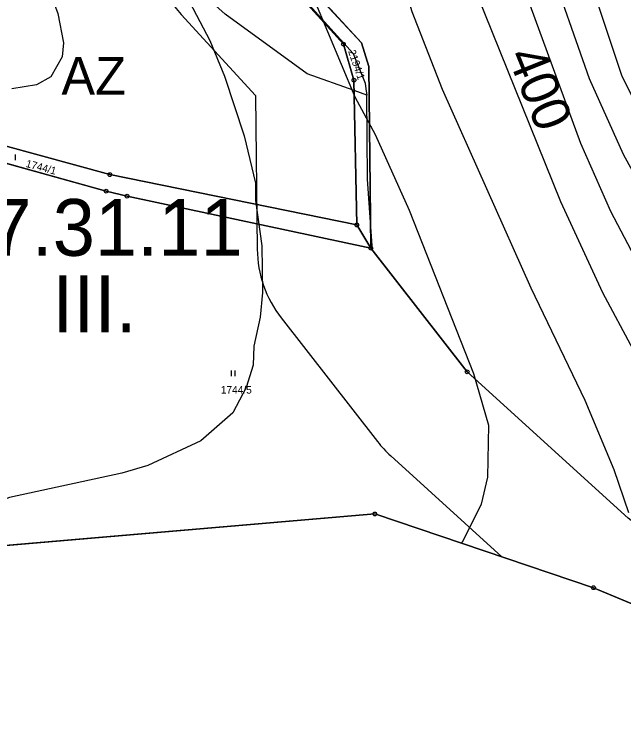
# Model space of a CAD drawing. Extents: x -706130 to -698555, y -971544 to -967260.
# Drawn here: x -703308.5 to -703147.5, y -971046.6 to -970857.1 of the extents above; entities that cross this region are included whole.
import ezdxf

# ---------------------------------------------------------------- set-up
doc = ezdxf.new("R2010")
doc.units = 0
for name, color, linetype in [('BPEJ hranice S', 7, 'Continuous'), ('BPEJ kód', 7, 'Continuous'), ('Hranice řešeného území', 7, 'Continuous'), ('KN_Hranice obce', 7, 'Continuous'), ('KN_Hranice_katastrální území', 7, 'Continuous'), ('KN_Hranice_parcel', 7, 'Continuous'), ('KN_Parcelni cisla', 7, 'Continuous'), ('KN_Polygon parcely', 7, 'Continuous'), ('KN_POZEMKY_10_LESNI POZEMEK', 7, 'Continuous'), ('KN_POZEMKY_14_OSTATNI PLOCHA', 7, 'Continuous'), ('KN_POZEMKY_7_TTP', 7, 'Continuous'), ('KN_VYUZITI_17_ostatni plocha_ostatni komunikace', 7, 'Continuous'), ('KN_Značky bodu BP', 7, 'Continuous'), ('KN_Značky kultur', 7, 'Continuous'), ('OP lesa 30 m', 7, 'Continuous'), ('Plochy lesní všeobecné S', 7, 'Continuous'), ('Plochy smíšené nezastavěného území všeobecné S', 7, 'Continuous'), ('Plochy zemědělské všeobecné CELEK S', 7, 'Continuous'), ('Povodi vodniho toku S', 7, 'Continuous'), ('Regulační bloky v krajině S', 7, 'Continuous'), ('Regulační kódy v krajině S', 7, 'Continuous'), ('VÝŠKOPIS_vrstevnice hlavní', 7, 'Continuous'), ('VÝŠKOPIS_vrstevnice výška', 7, 'Continuous'), ('VÝŠKOPIS_vrstevnice zesílená', 7, 'Continuous')]:
    doc.layers.add(name, color=color, linetype=linetype)

msp = doc.modelspace()

# ---------------------------------------------------------------- linework, layer by layer
at = {"layer": 'BPEJ hranice S'}
for points in [[(-703146.34, -970990.21), (-703188.87, -970951.52), (-703213.89, -970919.41), (-703214.4, -970912.01), (-703215.2, -970900.58), (-703215.37, -970878.39), (-703218.72, -970877.19), (-703231.11, -970872.76), (-703252.79, -970857.03), (-703269.59, -970841.85), (-703291.81, -970808.23), (-703299.14, -970791.84), (-703301.03, -970787.62), (-703323.79, -970764.31)], [(-703238.22, -970846.15), (-703219.02, -970867.46), (-703215.83, -970875.27), (-703215.61, -970876.73), (-703215.37, -970878.39), (-703218.72, -970877.19), (-703231.11, -970872.76), (-703252.79, -970857.03)], [(-703382.49, -970993.97), (-703382.44, -970993.97), (-703380.74, -970993.98), (-703327.73, -970998.95), (-703314.92, -970997.75), (-703213.28, -970989.07), (-703155.48, -971008.55), (-703136.46, -971016.54), (-703118.51, -971025.64), (-703110.66, -971029.62)]]:
    msp.add_lwpolyline(points, dxfattribs=at)
at = {"layer": 'Hranice řešeného území'}
msp.add_lwpolyline([(-703136.46, -971016.54), (-703155.48, -971008.55), (-703213.28, -970989.07), (-703314.92, -970997.75), (-703327.73, -970998.95), (-703380.74, -970993.98), (-703382.44, -970993.97), (-703386.57, -970993.95), (-703392.54, -970993.91), (-703394.33, -970993.9), (-703405.07, -970994.15), (-703417, -970993.25), (-703427.1, -970990.31), (-703478.14, -970955.69), (-703518.72, -970928.16), (-703520.57, -970926.9), (-703526.54, -970922.83), (-703552.19, -970905.36), (-703588.47, -970877.49), (-703614.35, -970903.64), (-703634.1, -970919.81)], dxfattribs=at)
at = {"layer": 'KN_Hranice obce'}
msp.add_lwpolyline([(-703634.1, -970919.81), (-703614.35, -970903.64), (-703588.47, -970877.49), (-703552.19, -970905.36), (-703526.54, -970922.83), (-703520.57, -970926.9), (-703518.72, -970928.16), (-703478.14, -970955.69), (-703427.1, -970990.31), (-703417, -970993.25), (-703405.07, -970994.15), (-703394.33, -970993.9), (-703392.54, -970993.91), (-703386.57, -970993.95), (-703382.44, -970993.97), (-703380.74, -970993.98), (-703327.73, -970998.95), (-703314.92, -970997.75), (-703213.28, -970989.07), (-703155.48, -971008.55), (-703136.46, -971016.54)], dxfattribs=at)
at = {"layer": 'KN_Hranice_katastrální území'}
msp.add_lwpolyline([(-703634.1, -970919.81), (-703614.35, -970903.64), (-703588.47, -970877.49), (-703552.19, -970905.36), (-703526.54, -970922.83), (-703520.57, -970926.9), (-703518.72, -970928.16), (-703478.14, -970955.69), (-703427.1, -970990.31), (-703417, -970993.25), (-703405.07, -970994.15), (-703394.33, -970993.9), (-703392.54, -970993.91), (-703386.57, -970993.95), (-703382.44, -970993.97), (-703380.74, -970993.98), (-703327.73, -970998.95), (-703314.92, -970997.75), (-703213.28, -970989.07), (-703155.48, -971008.55), (-703136.46, -971016.54)], dxfattribs=at)
at = {"layer": 'KN_Hranice_parcel'}
for p, q in [((-703283.26, -970899.43), (-703311.29, -970891.69)), ((-703218.04, -970912.72), (-703283.26, -970899.43)), ((-703278.74, -970905.1), (-703214.33, -970918.84)), ((-703214.33, -970918.84), (-703218.04, -970912.72))]:
    msp.add_line(p, q, dxfattribs=at)
for points in [[(-703218.04, -970912.72), (-703218.77, -970874.45), (-703221.56, -970864.95), (-703246.9, -970836.79)], [(-703242.32, -970836.8), (-703216.79, -970864.63), (-703214.84, -970870.83), (-703214.33, -970918.84)], [(-703324.83, -970892.5), (-703284.24, -970903.8), (-703278.74, -970905.1)], [(-703118.51, -971025.64), (-703116.04, -971013.3), (-703138.08, -970996.69), (-703146.34, -970990.21), (-703188.87, -970951.52), (-703214.33, -970918.84)], [(-703314.92, -970997.75), (-703213.28, -970989.07), (-703155.48, -971008.55), (-703136.46, -971016.54), (-703118.51, -971025.64)]]:
    msp.add_lwpolyline(points, dxfattribs=at)
at = {"layer": 'KN_Polygon parcely'}
msp.add_lwpolyline([(-703142.86, -970683.51), (-703168.87, -970735.8), (-703193.88, -970758.14), (-703201.19, -970768.01), (-703208.3, -970792.34), (-703211.64, -970831.19), (-703242.32, -970836.8), (-703216.79, -970864.63), (-703214.84, -970870.83), (-703214.33, -970918.84), (-703188.87, -970951.52), (-703146.34, -970990.21)], dxfattribs=at)
for points in [[(-703218.77, -970874.45), (-703221.56, -970864.95), (-703246.9, -970836.79), (-703252.48, -970822.52), (-703251.36, -970811.71), (-703338.12, -970775.63), (-703354.08, -970769.21), (-703356.16, -970787.98), (-703355, -970796.22), (-703358.84, -970830.72), (-703361.41, -970853.84), (-703322.73, -970883.71), (-703325.48, -970887.18), (-703311.29, -970891.69), (-703283.26, -970899.43), (-703218.04, -970912.72)], [(-703246.9, -970836.79), (-703221.56, -970864.95), (-703218.77, -970874.45), (-703218.04, -970912.72), (-703214.33, -970918.84), (-703214.84, -970870.83), (-703216.79, -970864.63), (-703242.32, -970836.8)], [(-703218.04, -970912.72), (-703283.26, -970899.43), (-703311.29, -970891.69), (-703325.48, -970887.18), (-703359.8, -970881.15), (-703359.88, -970886.03), (-703324.83, -970892.5), (-703284.24, -970903.8), (-703278.74, -970905.1), (-703214.33, -970918.84)], [(-703116.04, -971013.3), (-703138.08, -970996.69), (-703146.34, -970990.21), (-703188.87, -970951.52), (-703214.33, -970918.84), (-703278.74, -970905.1), (-703284.24, -970903.8), (-703324.83, -970892.5), (-703359.88, -970886.03), (-703368.03, -970914.24), (-703318.27, -970925.22), (-703314.92, -970997.75), (-703213.28, -970989.07), (-703155.48, -971008.55), (-703136.46, -971016.54), (-703118.51, -971025.64)]]:
    msp.add_lwpolyline(points, close=True, dxfattribs=at)
at = {"layer": 'KN_POZEMKY_10_LESNI POZEMEK'}
for p, q in [((-703216.79, -970864.63), (-703242.32, -970836.8)), ((-703214.84, -970870.83), (-703216.79, -970864.63)), ((-703214.33, -970918.84), (-703214.84, -970870.83)), ((-703188.87, -970951.52), (-703214.33, -970918.84)), ((-703146.34, -970990.21), (-703188.87, -970951.52))]:
    msp.add_line(p, q, dxfattribs=at)
at = {"layer": 'KN_POZEMKY_14_OSTATNI PLOCHA'}
for p, q in [((-703221.56, -970864.95), (-703246.9, -970836.79)), ((-703242.32, -970836.8), (-703216.79, -970864.63)), ((-703218.77, -970874.45), (-703221.56, -970864.95)), ((-703216.79, -970864.63), (-703214.84, -970870.83)), ((-703214.84, -970870.83), (-703214.33, -970918.84)), ((-703218.04, -970912.72), (-703218.77, -970874.45)), ((-703214.33, -970918.84), (-703218.04, -970912.72))]:
    msp.add_line(p, q, dxfattribs=at)
at = {"layer": 'KN_POZEMKY_7_TTP'}
for p, q in [((-703246.9, -970836.79), (-703221.56, -970864.95)), ((-703221.56, -970864.95), (-703218.77, -970874.45)), ((-703218.77, -970874.45), (-703218.04, -970912.72)), ((-703284.24, -970903.8), (-703324.83, -970892.5)), ((-703324.83, -970892.5), (-703284.24, -970903.8)), ((-703311.29, -970891.69), (-703283.26, -970899.43)), ((-703283.26, -970899.43), (-703311.29, -970891.69)), ((-703283.26, -970899.43), (-703218.04, -970912.72)), ((-703218.04, -970912.72), (-703283.26, -970899.43)), ((-703278.74, -970905.1), (-703284.24, -970903.8)), ((-703284.24, -970903.8), (-703278.74, -970905.1)), ((-703214.33, -970918.84), (-703278.74, -970905.1)), ((-703278.74, -970905.1), (-703214.33, -970918.84)), ((-703218.04, -970912.72), (-703214.33, -970918.84)), ((-703214.33, -970918.84), (-703188.87, -970951.52)), ((-703188.87, -970951.52), (-703146.34, -970990.21)), ((-703213.28, -970989.07), (-703314.92, -970997.75)), ((-703155.48, -971008.55), (-703213.28, -970989.07)), ((-703136.46, -971016.54), (-703155.48, -971008.55))]:
    msp.add_line(p, q, dxfattribs=at)
at = {"layer": 'KN_VYUZITI_17_ostatni plocha_ostatni komunikace'}
for p, q in [((-703221.56, -970864.95), (-703246.9, -970836.79)), ((-703242.32, -970836.8), (-703216.79, -970864.63)), ((-703218.77, -970874.45), (-703221.56, -970864.95)), ((-703216.79, -970864.63), (-703214.84, -970870.83)), ((-703214.84, -970870.83), (-703214.33, -970918.84)), ((-703218.04, -970912.72), (-703218.77, -970874.45)), ((-703214.33, -970918.84), (-703218.04, -970912.72))]:
    msp.add_line(p, q, dxfattribs=at)
at = {"layer": 'KN_Značky bodu BP'}
for centre, radius in [((-703221.56, -970864.95), 0.5), ((-703221.56, -970864.95), 0.0303), ((-703218.77, -970874.45), 0.5), ((-703218.77, -970874.45), 0.0303), ((-703283.26, -970899.43), 0.5), ((-703283.26, -970899.43), 0.0303), ((-703284.24, -970903.8), 0.5), ((-703284.24, -970903.8), 0.0303), ((-703278.74, -970905.1), 0.5), ((-703278.74, -970905.1), 0.0303), ((-703218.04, -970912.72), 0.5), ((-703218.04, -970912.72), 0.0303), ((-703214.33, -970918.84), 0.5), ((-703214.33, -970918.84), 0.0303), ((-703188.87, -970951.52), 0.5), ((-703188.87, -970951.52), 0.0303), ((-703213.28, -970989.07), 0.5), ((-703213.28, -970989.07), 0.0303), ((-703155.48, -971008.55), 0.5), ((-703155.48, -971008.55), 0.0303)]:
    msp.add_circle(centre, radius, dxfattribs=at)
at = {"layer": 'KN_Značky kultur'}
for p, q in [((-703308.16, -970895.59), (-703308.16, -970894.09)), ((-703251.13, -970952.69), (-703251.13, -970951.19)), ((-703250.13, -970952.69), (-703250.13, -970951.19))]:
    msp.add_line(p, q, dxfattribs=at)
at = {"layer": 'OP lesa 30 m'}
for p, q in [((-703238, -970937.28), (-703212.54, -970969.96)), ((-703209.06, -970973.71), (-703179.75, -971000.37))]:
    msp.add_line(p, q, dxfattribs=at)
msp.add_lwpolyline([(-703264.43, -970857.08), (-703244.76, -970878.52), (-703244.33, -970919.16)], dxfattribs=at)
for centre, start, end in [((-703242.32, -970836.8), 100.3624, 222.5319), ((-703214.33, -970918.84), 180.6086, 217.9211), ((-703188.87, -970951.52), 217.9211, 227.7069)]:
    msp.add_arc(centre, 30, start, end, dxfattribs=at)
at = {"layer": 'Plochy lesní všeobecné S'}
for p, q in [((-703242.32, -970836.8), (-703216.79, -970864.63)), ((-703216.79, -970864.63), (-703214.84, -970870.83)), ((-703214.84, -970870.83), (-703214.33, -970918.84)), ((-703214.33, -970918.84), (-703188.87, -970951.52)), ((-703188.87, -970951.52), (-703146.34, -970990.21))]:
    msp.add_line(p, q, dxfattribs=at)
at = {"layer": 'Plochy smíšené nezastavěného území všeobecné S'}
for p, q in [((-703246.9, -970836.79), (-703221.56, -970864.95)), ((-703221.56, -970864.95), (-703218.77, -970874.45)), ((-703218.77, -970874.45), (-703218.04, -970912.72))]:
    msp.add_line(p, q, dxfattribs=at)
for points in [[(-703214.84, -970870.83), (-703216.79, -970864.63), (-703242.32, -970836.8)], [(-703218.04, -970912.72), (-703214.33, -970918.84), (-703214.84, -970870.83)]]:
    msp.add_lwpolyline(points, dxfattribs=at)
at = {"layer": 'Plochy zemědělské všeobecné CELEK S'}
for p, q in [((-703221.56, -970864.95), (-703246.9, -970836.79)), ((-703218.77, -970874.45), (-703221.56, -970864.95)), ((-703218.04, -970912.72), (-703218.77, -970874.45)), ((-703214.33, -970918.84), (-703218.04, -970912.72)), ((-703188.87, -970951.52), (-703214.33, -970918.84)), ((-703146.34, -970990.21), (-703188.87, -970951.52)), ((-703314.92, -970997.75), (-703213.28, -970989.07)), ((-703213.28, -970989.07), (-703155.48, -971008.55)), ((-703155.48, -971008.55), (-703136.46, -971016.54))]:
    msp.add_line(p, q, dxfattribs=at)
at = {"layer": 'Povodi vodniho toku S'}
msp.add_lwpolyline([(-703634.1, -970919.81), (-703614.35, -970903.64), (-703588.47, -970877.49), (-703552.19, -970905.36), (-703526.54, -970922.83), (-703520.57, -970926.9), (-703518.72, -970928.16), (-703478.14, -970955.69), (-703427.1, -970990.31), (-703417, -970993.25), (-703405.07, -970994.15), (-703394.33, -970993.9), (-703392.54, -970993.91), (-703386.57, -970993.95), (-703382.44, -970993.97), (-703380.74, -970993.98), (-703327.73, -970998.95), (-703314.92, -970997.75), (-703213.28, -970989.07), (-703155.48, -971008.55), (-703136.46, -971016.54)], dxfattribs=at)
at = {"layer": 'Regulační bloky v krajině S'}
for p, q in [((-703246.9, -970836.79), (-703221.56, -970864.95)), ((-703221.56, -970864.95), (-703246.9, -970836.79)), ((-703242.32, -970836.8), (-703216.79, -970864.63)), ((-703221.56, -970864.95), (-703218.77, -970874.45)), ((-703218.77, -970874.45), (-703221.56, -970864.95)), ((-703216.79, -970864.63), (-703214.84, -970870.83)), ((-703214.84, -970870.83), (-703214.33, -970918.84)), ((-703218.77, -970874.45), (-703218.04, -970912.72)), ((-703218.04, -970912.72), (-703218.77, -970874.45)), ((-703214.33, -970918.84), (-703218.04, -970912.72)), ((-703214.33, -970918.84), (-703188.87, -970951.52)), ((-703188.87, -970951.52), (-703214.33, -970918.84)), ((-703188.87, -970951.52), (-703146.34, -970990.21)), ((-703146.34, -970990.21), (-703188.87, -970951.52)), ((-703314.92, -970997.75), (-703213.28, -970989.07)), ((-703213.28, -970989.07), (-703155.48, -971008.55)), ((-703155.48, -971008.55), (-703136.46, -971016.54))]:
    msp.add_line(p, q, dxfattribs=at)
for points in [[(-703214.84, -970870.83), (-703216.79, -970864.63), (-703242.32, -970836.8)], [(-703218.04, -970912.72), (-703214.33, -970918.84), (-703214.84, -970870.83)]]:
    msp.add_lwpolyline(points, dxfattribs=at)
at = {"layer": 'VÝŠKOPIS_vrstevnice hlavní'}
for points in [[(-703198.72, -970576.45), (-703211.02, -970605.08), (-703213.45, -970624.92), (-703214.16, -970648.88), (-703216.01, -970666.57), (-703222.43, -970700.82), (-703234.99, -970741.91), (-703239.41, -970759.88), (-703241.27, -970773.86), (-703241.69, -970793.98), (-703242.26, -970794.12), (-703241.69, -970794.41), (-703240.98, -970806.96), (-703237.98, -970824.94), (-703229.42, -970852.9), (-703218.58, -970878.87), (-703213.16, -970888.86), (-703204.17, -970908.83), (-703187.19, -970951.92), (-703183.2, -970965.61), (-703183.48, -970979.31), (-703185.2, -970986.44), (-703190.05, -970996.29), (-703190.45, -970996.77)], [(-703162.26, -970590.2), (-703172.07, -970600.66), (-703177.92, -970609.79), (-703180.06, -970614.36), (-703181.77, -970621.21), (-703185.05, -970641.75), (-703185.77, -970664.58), (-703187.05, -970680.56), (-703190.19, -970698.82), (-703196.75, -970723.93), (-703204.46, -970744.47), (-703210.45, -970758.17), (-703214.3, -970769.58), (-703217.15, -970785.56), (-703217.15, -970799.26), (-703214.3, -970817.52), (-703210.45, -970833.5), (-703203.46, -970856.33), (-703195.47, -970876.87), (-703172.07, -970929.37), (-703157.8, -970959.05), (-703150.1, -970977.31), (-703146.25, -970988.72)], [(-703256.82, -970608.94), (-703254.68, -970630.05), (-703254.68, -970638.9), (-703256.39, -970661.72), (-703258.39, -970675.99), (-703263.24, -970695.96), (-703278.5, -970738.77), (-703284.78, -970762.16), (-703286.63, -970780.43), (-703285.49, -970794.69), (-703280.21, -970814.67), (-703273.79, -970831.79), (-703256.82, -970864.03), (-703252.96, -970873.45), (-703247.83, -970889.14), (-703244.83, -970901.7), (-703244.83, -970906.26), (-703243.12, -970918.25), (-703242.98, -970930.52), (-703243.55, -970937.08), (-703245.26, -970944.78), (-703245.4, -970949.78), (-703247.26, -970955.63), (-703250.82, -970962.33)], [(-703084.36, -970625.93), (-703101.73, -970634.62), (-703114.29, -970644.89), (-703124.56, -970657.16), (-703135.05, -970673.35), (-703141.25, -970685.69), (-703148.53, -970702.81), (-703159.66, -970734.2), (-703168.65, -970754.18), (-703174.92, -970770.15), (-703180.06, -970790.13), (-703181.77, -970804.11), (-703181.2, -970818.66), (-703177.21, -970839.21), (-703174.21, -970849.19), (-703158.94, -970891.14), (-703150.96, -970909.12), (-703144.68, -970921.1), (-703102.73, -970989.87), (-703093.03, -971009.27), (-703086.33, -971024.68), (-703082.9, -971034.95), (-703082.05, -971043.51), (-703082.43, -971046.58)], [(-703141.54, -970732.2), (-703155.52, -970756.6), (-703163.51, -970773.44), (-703168.5, -970789.27), (-703171.36, -970805.25), (-703171.93, -970816.95), (-703169.93, -970832.64), (-703167.79, -970842.06), (-703156.66, -970874.02), (-703147.67, -970893.99), (-703137.83, -970911.97)], [(-703147.1, -970759.03), (-703156.52, -970777.29), (-703159.8, -970786.42), (-703162.94, -970806.96), (-703162.94, -970816.09), (-703162.23, -970822.94), (-703155.66, -970850.34), (-703148.1, -970873.16), (-703139.11, -970891.42)], [(-703318.17, -970808.1), (-703306.47, -970831.22), (-703297.05, -970856.9), (-703295.48, -970864.6), (-703295.91, -970868.31), (-703298.9, -970873.59), (-703302.61, -970875.73), (-703309.18, -970876.73)], [(-703250.82, -970962.33), (-703259.24, -970969.75), (-703273.22, -970976.31), (-703280.07, -970978.31), (-703309.75, -970984.73), (-703327.01, -970991.01), (-703337.14, -970997), (-703338.18, -970997.97)]]:
    msp.add_lwpolyline(points, dxfattribs=at)
at = {"layer": 'VÝŠKOPIS_vrstevnice zesílená'}
msp.add_lwpolyline([(-703150.38, -970633.76), (-703154.24, -970645.75), (-703157.23, -970657.73), (-703163.37, -970693.68), (-703171.36, -970723.64), (-703182.06, -970747.61), (-703191.19, -970772.15), (-703192.76, -970778.43), (-703195.18, -970803.54), (-703194.9, -970816.09), (-703193.19, -970828.65), (-703188.34, -970846.63), (-703164.22, -970906.55), (-703153.1, -970930.52), (-703137.12, -970960.48), (-703122.71, -970984.45), (-703116.57, -970997), (-703111.58, -971009.56), (-703110.15, -971015.83), (-703109.58, -971022.11), (-703110.01, -971028.39), (-703110.43, -971029.75)], dxfattribs=at)

# ---------------------------------------------------------------- texts
at = {"layer": 'BPEJ kód'}
for s, p in [('7.31.11', (-703315.09, -970920.87)), ('III.', (-703298.48, -970941.06))]:
    msp.add_text(s, height=15, dxfattribs=at).set_placement(p)
at = {"layer": 'KN_Parcelni cisla'}
for s, rotation, p in [('2194/1', 289, (-703220.36, -970866.82)), ('1744/1', 345, (-703305.63, -970897.36))]:
    msp.add_text(s, height=2, rotation=rotation, dxfattribs=at).set_placement(p)
msp.add_text('1744/5', height=2, dxfattribs=at).set_placement((-703253.96, -970957.28))
at = {"layer": 'Regulační kódy v krajině S'}
msp.add_text('AZ', height=10, dxfattribs=at).set_placement((-703296.08, -970878.34))
at = {"layer": 'VÝŠKOPIS_vrstevnice výška'}
msp.add_text('400', height=10, rotation=291.9193, dxfattribs=at).set_placement((-703178.38, -970868.01))

doc.saveas('drawing.dxf')
